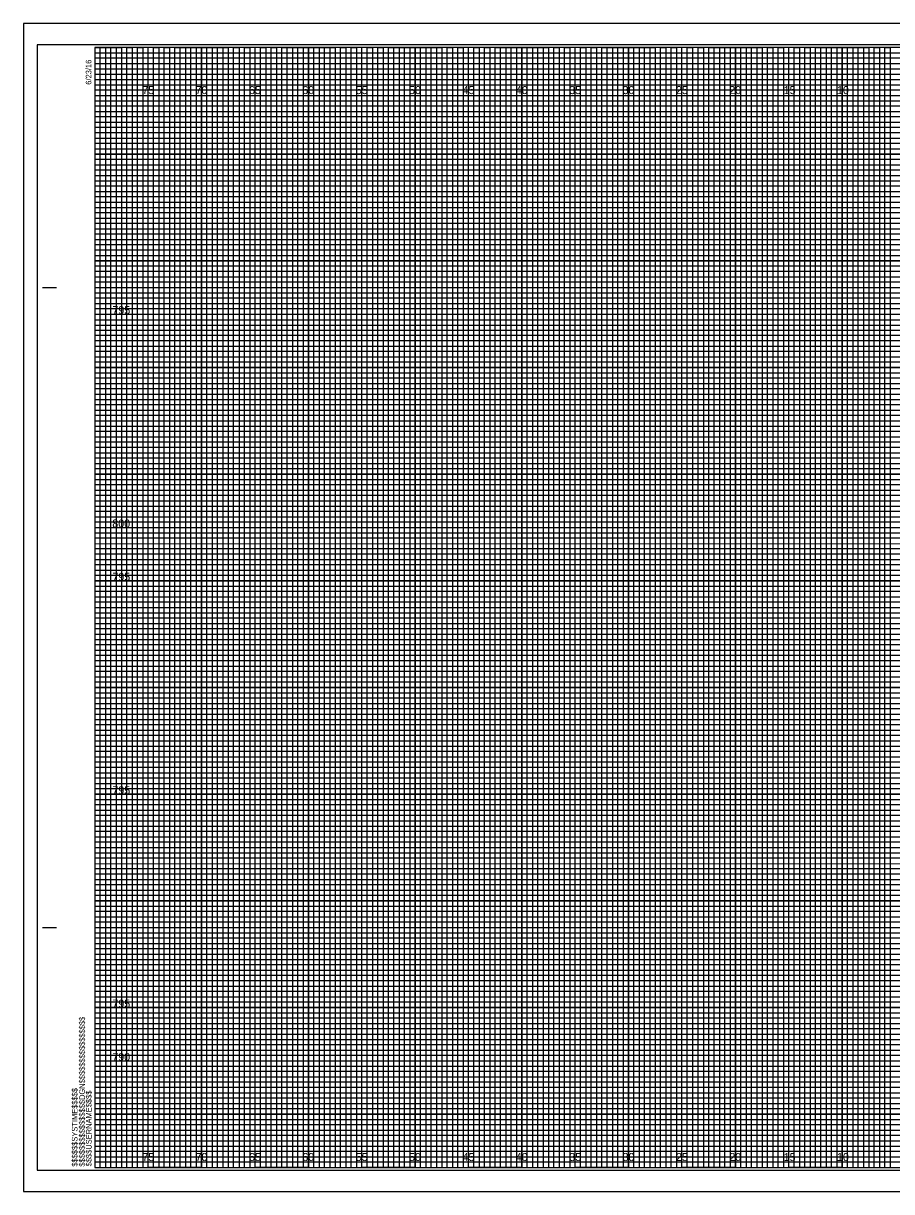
# Model space of a CAD drawing. Extents: x -7 to 162, y -2 to 107.
# Drawn here: x -6.7 to 74.6, y -2.3 to 107.3 of the extents above; entities that cross this region are included whole.
import ezdxf

# ---------------------------------------------------------------- set-up
doc = ezdxf.new("R2010")
doc.units = 0
for name, color, linetype in [('Exist Cross Section Cell', 7, 'Continuous'), ('Exist XS Center Line Elevation Label', 7, 'Continuous'), ('Prop CMT Pvmt Course 2 Wedge', 7, 'Continuous'), ('Prop CMT Pvmt Surface Shoulder', 7, 'Continuous'), ('Prop CMT Shld Paved Course 1', 7, 'Continuous'), ('Prop CMT Shld Paved Course 3', 7, 'Continuous'), ('Prop XS Hydro Elevations', 7, 'Continuous'), ('Prop XS SE Text', 7, 'Continuous'), ('Prop XS Side Slope Text', 7, 'Continuous'), ('Sheet Cutting Line CELL', 7, 'Continuous'), ('Sheet DOT Grid CELL', 7, 'Continuous')]:
    doc.layers.add(name, color=color, linetype=linetype)

msp = doc.modelspace()

# ---------------------------------------------------------------- linework, layer by layer
at = {"layer": 'Exist Cross Section Cell'}
for p, q in [((5, 105), (0, 105)), ((5, 0), (5, 105)), ((15, 105), (10, 105)), ((10, 105), (10, 0)), ((15, 0), (15, 105)), ((25, 105), (20, 105)), ((20, 105), (20, 0)), ((25, 0), (25, 105)), ((35, 105), (30, 105)), ((30, 105), (30, 0)), ((35, 0), (35, 105)), ((45, 105), (40, 105)), ((40, 105), (40, 0)), ((45, 0), (45, 105)), ((55, 105), (50, 105)), ((50, 105), (50, 0)), ((55, 0), (55, 105)), ((65, 105), (60, 105)), ((60, 105), (60, 0)), ((65, 0), (65, 105)), ((75, 105), (70, 105)), ((70, 105), (70, 0)), ((10, 0), (5, 0)), ((20, 0), (15, 0)), ((30, 0), (25, 0)), ((40, 0), (35, 0)), ((50, 0), (45, 0)), ((60, 0), (55, 0)), ((70, 0), (65, 0))]:
    msp.add_line(p, q, dxfattribs=at)
for points in [[(0, 100), (160, 100), (160, 95), (0, 95)], [(0, 90), (160, 90), (160, 85), (0, 85)], [(0, 80), (160, 80), (160, 75), (0, 75)], [(0, 70), (160, 70), (160, 65), (0, 65)], [(0, 60), (160, 60), (160, 55), (0, 55)], [(0, 50), (160, 50), (160, 45), (0, 45)], [(0, 40), (160, 40), (160, 35), (0, 35)], [(0, 30), (160, 30), (160, 25), (0, 25)], [(0, 20), (160, 20), (160, 15), (0, 15)], [(0, 10), (160, 10), (160, 5), (0, 5)]]:
    msp.add_lwpolyline(points, dxfattribs=at)
at = {"layer": 'Exist XS Center Line Elevation Label'}
for points in [[(0, 105), (2.5, 105), (2.5, 0), (7.5, 0), (7.5, 105), (12.5, 105), (12.5, 0), (17.5, 0), (17.5, 105), (22.5, 105), (22.5, 0), (27.5, 0), (27.5, 105), (32.5, 105), (32.5, 0), (37.5, 0), (37.5, 105), (42.5, 105), (42.5, 0), (47.5, 0), (47.5, 105), (52.5, 105), (52.5, 0), (57.5, 0), (57.5, 105), (62.5, 105), (62.5, 0), (67.5, 0), (67.5, 105), (72.5, 105), (72.5, 0), (77.5, 0)], [(0, 102.5), (137.5, 102.5)], [(0, 92.5), (160, 92.5), (160, 97.5), (0, 97.5)], [(0, 82.5), (160, 82.5), (160, 87.5), (0, 87.5)], [(0, 72.5), (160, 72.5), (160, 77.5), (0, 77.5)], [(0, 62.5), (160, 62.5), (160, 67.5), (0, 67.5)], [(0, 52.5), (160, 52.5), (160, 57.5), (0, 57.5)], [(0, 42.5), (160, 42.5), (160, 47.5), (0, 47.5)], [(0, 32.5), (160, 32.5), (160, 37.5), (0, 37.5)], [(0, 22.5), (160, 22.5), (160, 27.5), (0, 27.5)], [(0, 12.5), (160, 12.5), (160, 17.5), (0, 17.5)], [(0, 2.5), (160, 2.5), (160, 7.5), (0, 7.5)]]:
    msp.add_lwpolyline(points, dxfattribs=at)
at = {"layer": 'Prop CMT Pvmt Surface Shoulder'}
msp.add_lwpolyline([(-5.4, -0.25), (161.2, -0.25), (161.2, 105.25), (-5.4, 105.25)], close=True, dxfattribs=at)
at = {"layer": 'Prop CMT Shld Paved Course 1'}
for points in [[(0, 0), (0.5, 0), (0.5, 105), (1, 105), (1, 0)], [(1, 0), (1.5, 0), (1.5, 105), (2, 105), (2, 0)], [(2.5, 0), (3, 0), (3, 105), (3.5, 105), (3.5, 0)], [(3.5, 0), (4, 0), (4, 105), (4.5, 105), (4.5, 0)], [(5, 0), (5.5, 0), (5.5, 105), (6, 105), (6, 0)], [(6, 0), (6.5, 0), (6.5, 105), (7, 105), (7, 0)], [(7.5, 0), (8, 0), (8, 105), (8.5, 105), (8.5, 0)], [(8.5, 0), (9, 0), (9, 105), (9.5, 105), (9.5, 0)], [(10, 0), (10.5, 0), (10.5, 105), (11, 105), (11, 0)], [(11, 0), (11.5, 0), (11.5, 105), (12, 105), (12, 0)], [(12.5, 0), (13, 0), (13, 105), (13.5, 105), (13.5, 0)], [(13.5, 0), (14, 0), (14, 105), (14.5, 105), (14.5, 0)], [(15, 0), (15.5, 0), (15.5, 105), (16, 105), (16, 0)], [(16, 0), (16.5, 0), (16.5, 105), (17, 105), (17, 0)], [(17.5, 0), (18, 0), (18, 105), (18.5, 105), (18.5, 0)], [(18.5, 0), (19, 0), (19, 105), (19.5, 105), (19.5, 0)], [(20, 0), (20.5, 0), (20.5, 105), (21, 105), (21, 0)], [(21, 0), (21.5, 0), (21.5, 105), (22, 105), (22, 0)], [(22.5, 0), (23, 0), (23, 105), (23.5, 105), (23.5, 0)], [(23.5, 0), (24, 0), (24, 105), (24.5, 105), (24.5, 0)], [(25, 0), (25.5, 0), (25.5, 105), (26, 105), (26, 0)], [(26, 0), (26.5, 0), (26.5, 105), (27, 105), (27, 0)], [(27.5, 0), (28, 0), (28, 105), (28.5, 105), (28.5, 0)], [(28.5, 0), (29, 0), (29, 105), (29.5, 105), (29.5, 0)], [(30, 0), (30.5, 0), (30.5, 105), (31, 105), (31, 0)], [(31, 0), (31.5, 0), (31.5, 105), (32, 105), (32, 0)], [(32.5, 0), (33, 0), (33, 105), (33.5, 105), (33.5, 0)], [(33.5, 0), (34, 0), (34, 105), (34.5, 105), (34.5, 0)], [(35, 0), (35.5, 0), (35.5, 105), (36, 105), (36, 0)], [(36, 0), (36.5, 0), (36.5, 105), (37, 105), (37, 0)], [(37.5, 0), (38, 0), (38, 105), (38.5, 105), (38.5, 0)], [(38.5, 0), (39, 0), (39, 105), (39.5, 105), (39.5, 0)], [(40, 0), (40.5, 0), (40.5, 105), (41, 105), (41, 0)], [(41, 0), (41.5, 0), (41.5, 105), (42, 105), (42, 0)], [(42.5, 0), (43, 0), (43, 105), (43.5, 105), (43.5, 0)], [(43.5, 0), (44, 0), (44, 105), (44.5, 105), (44.5, 0)], [(45, 0), (45.5, 0), (45.5, 105), (46, 105), (46, 0)], [(46, 0), (46.5, 0), (46.5, 105), (47, 105), (47, 0)], [(47.5, 0), (48, 0), (48, 105), (48.5, 105), (48.5, 0)], [(48.5, 0), (49, 0), (49, 105), (49.5, 105), (49.5, 0)], [(50, 0), (50.5, 0), (50.5, 105), (51, 105), (51, 0)], [(51, 0), (51.5, 0), (51.5, 105), (52, 105), (52, 0)], [(52.5, 0), (53, 0), (53, 105), (53.5, 105), (53.5, 0)], [(53.5, 0), (54, 0), (54, 105), (54.5, 105), (54.5, 0)], [(55, 0), (55.5, 0), (55.5, 105), (56, 105), (56, 0)], [(56, 0), (56.5, 0), (56.5, 105), (57, 105), (57, 0)], [(57.5, 0), (58, 0), (58, 105), (58.5, 105), (58.5, 0)], [(58.5, 0), (59, 0), (59, 105), (59.5, 105), (59.5, 0)], [(60, 0), (60.5, 0), (60.5, 105), (61, 105), (61, 0)], [(61, 0), (61.5, 0), (61.5, 105), (62, 105), (62, 0)], [(62.5, 0), (63, 0), (63, 105), (63.5, 105), (63.5, 0)], [(63.5, 0), (64, 0), (64, 105), (64.5, 105), (64.5, 0)], [(65, 0), (65.5, 0), (65.5, 105), (66, 105), (66, 0)], [(66, 0), (66.5, 0), (66.5, 105), (67, 105), (67, 0)], [(67.5, 0), (68, 0), (68, 105), (68.5, 105), (68.5, 0)], [(68.5, 0), (69, 0), (69, 105), (69.5, 105), (69.5, 0)], [(70, 0), (70.5, 0), (70.5, 105), (71, 105), (71, 0)], [(71, 0), (71.5, 0), (71.5, 105), (72, 105), (72, 0)], [(72.5, 0), (73, 0), (73, 105), (73.5, 105), (73.5, 0)], [(73.5, 0), (74, 0), (74, 105), (74.5, 105), (74.5, 0)]]:
    msp.add_lwpolyline(points, dxfattribs=at)
at = {"layer": 'Prop CMT Shld Paved Course 3'}
msp.add_lwpolyline([(-6.7, -2.25), (161.65, -2.25), (161.65, 107.25), (-6.7, 107.25)], close=True, dxfattribs=at)
at = {"layer": 'Prop XS Hydro Elevations'}
for p, q in [((-4.9, 82.5), (-3.65, 82.5)), ((-4.85, 82.5), (-3.6, 82.5)), ((-4.9, 22.5), (-3.65, 22.5)), ((-4.85, 22.5), (-3.6, 22.5)), ((0, 0), (0, 0)), ((0, 0), (0, 0)), ((0, 0), (0, 0)), ((0, 0), (0, 0)), ((0, 0), (0, 0)), ((0, 0), (0, 0)), ((0, 0), (0, 0))]:
    msp.add_line(p, q, dxfattribs=at)
msp.add_lwpolyline([(160, 105), (0, 105), (0, 0), (160, 0)], close=True, dxfattribs=at)
at = {"layer": 'Prop XS Side Slope Text'}
for p, q in [((0, 104.5), (130, 104.5)), ((130, 103.99), (0, 103.99)), ((0, 103.99), (0, 103.5)), ((0, 103.5), (130, 103.5)), ((130, 102.95), (0, 102.95)), ((0, 102.95), (0, 102)), ((0, 102), (160, 102))]:
    msp.add_line(p, q, dxfattribs=at)
for points in [[(0, 101.5), (135, 101.5), (160, 101.5), (160, 101), (0, 101)], [(0, 100.5), (160, 100.5), (160, 99.5), (0, 99.5)], [(0, 99), (160, 99), (160, 98.5), (0, 98.49)], [(0, 98), (160, 98), (160, 97), (0, 97)], [(0, 96.5), (160, 96.5), (160, 96), (0, 96)], [(0, 95.5), (160, 95.5), (160, 94.5), (0, 94.5)], [(0, 94), (160, 94), (160, 93.5), (0, 93.5)], [(0, 93), (160, 93), (160, 92), (0, 92)], [(0, 91.5), (160, 91.5), (160, 91), (0, 91)], [(0, 90.5), (160, 90.5), (160, 89.5), (0, 89.5)], [(0, 89), (160, 89), (160, 88.5), (0, 88.5)], [(0, 88), (160, 88), (160, 86.98), (160, 86.5), (160, 86), (0, 86)], [(0, 87), (160, 87), (160, 86.5), (0, 86.5)], [(0, 85.5), (160, 85.5), (160, 84.5), (0, 84.52)], [(0, 84.52), (160, 84.5), (160, 84), (0, 84)], [(0, 83.5), (160, 83.5), (160, 83), (0, 83)], [(0, 82), (160, 82), (160, 81.5), (0, 81.5)], [(0, 81), (160, 81), (160, 80.5), (0, 80.5)], [(-0.04, 79.45), (160, 79.45), (160, 78.94), (-0.04, 78.94)], [(0, 78.5), (160, 78.5), (160, 78), (0, 78)], [(0, 77), (160, 77), (160, 76.5), (0, 76.5)], [(0, 76), (160, 76), (160, 75.5), (0, 75.5)], [(0, 74.5), (160, 74.5), (160, 74), (0, 74)], [(0, 73.5), (160, 73.5), (160, 73), (0, 73)], [(0, 72), (160, 72), (160, 71.5), (0, 71.5)], [(0, 71), (160, 71), (160, 70.5), (0, 70.5)], [(0, 69.5), (160, 69.5), (160, 68.99), (0, 69)], [(0, 68.5), (160, 68.5), (160, 68), (0, 68)], [(0, 67), (160, 67), (160, 66.5), (0, 66.5)], [(0, 66), (160, 66), (160, 65.5), (0, 65.5)], [(0, 64.5), (160, 64.5), (160, 64), (0, 64)], [(0, 63.5), (160, 63.5), (160, 63), (0, 63)], [(0, 62), (160, 62), (160, 61.5), (0, 61.5)], [(0, 61), (160, 61), (160, 60.5), (0, 60.5)], [(0, 59.5), (160, 59.5), (160, 59), (0, 59)], [(0, 58.5), (160.03, 58.45), (160, 58), (0, 58)], [(0, 57), (160, 57), (160, 56.5), (0, 56.5)], [(0, 56), (160, 56), (160, 55.5), (0, 55.5)], [(0, 54.5), (160, 54.5), (160, 54), (0, 54)], [(0, 53.5), (160, 53.5), (160, 53), (0, 53)], [(0, 52), (160, 52), (160, 51.5), (0, 51.5)], [(0, 51), (160, 51), (160, 50.5), (0, 50.5)], [(0, 49.5), (160, 49.5), (160, 49), (0, 49)], [(0, 48.5), (160, 48.5), (160, 48), (0, 48)], [(0, 47), (160, 47), (160, 46.5), (0, 46.5)], [(0, 46), (160, 46), (160, 45.5), (0, 45.5)], [(0, 44.5), (160, 44.5), (160, 44), (0, 44)], [(0, 43.5), (160, 43.5), (160, 43), (0, 43)], [(0, 42), (160, 42), (160, 41.5), (0, 41.5)], [(0, 41), (160, 41), (160, 40.5), (0, 40.5)], [(0, 39.5), (160, 39.5), (160, 38.99), (0, 39)], [(0, 38.5), (160, 38.5), (160, 38), (0, 38)], [(0, 37), (160, 37), (160, 36.5), (0, 36.5)], [(0, 36), (160, 36), (160, 35.5), (0, 35.5)], [(0, 34.5), (160, 34.5), (160, 34), (0, 34)], [(0, 33.5), (160, 33.5), (160, 33), (0, 33)], [(0, 32), (160, 32), (160, 31.5), (0, 31.5)], [(0, 31), (160, 31), (160, 30.5), (0, 30.5)], [(0, 29.5), (160, 29.5), (160, 29), (0, 29)], [(0, 28.5), (160.03, 28.46), (160, 28), (0, 28)], [(0, 27), (160, 27), (160, 26.5), (0, 26.5)], [(0, 26), (160, 26), (160, 25.5), (0, 25.5)], [(0, 24.5), (160, 24.5), (160, 24), (0, 24)], [(0, 23.5), (160, 23.5), (160, 23), (0, 23)], [(0, 22), (160, 22), (160, 21.5), (0, 21.5)], [(0, 21), (160, 21), (160, 20.5), (0, 20.5)], [(0, 19.5), (160, 19.5), (160, 19), (0, 19)], [(0, 18.5), (160, 18.5), (160, 18), (0, 18)], [(0, 17), (160, 17), (160, 16.5), (0, 16.5)], [(0, 16), (160, 16), (160, 15.5), (0, 15.5)], [(0, 14.5), (160, 14.5), (160, 14), (0, 14)], [(0, 13.5), (160, 13.5), (160, 13), (0, 13)], [(0, 12), (160, 12), (160, 11.5), (0, 11.5)], [(0, 11), (160, 11), (160, 10.5), (0, 10.5)], [(0, 9.5), (160, 9.5), (160, 9), (0, 9)], [(0, 8.5), (160, 8.5), (160, 8), (0, 8)], [(0, 7), (160, 7), (160, 6.5), (0, 6.5)], [(0, 6), (160, 6), (160, 5.5), (0, 5.5)], [(0, 4.5), (160, 4.5), (160, 4), (0, 4)], [(0, 3.5), (160, 3.5), (160, 3), (0, 3)], [(0, 2), (160, 2), (160, 1.5), (0, 1.5)], [(0, 1), (160, 1), (160, 0.5), (0, 0.5)]]:
    msp.add_lwpolyline(points, dxfattribs=at)
at = {"layer": 'Sheet Cutting Line CELL'}
for p, q in [((161.65, 107.25), (-6.7, 107.25)), ((-6.7, 107.25), (-6.7, -2.25)), ((-6.7, -2.25), (161.65, -2.25))]:
    msp.add_line(p, q, dxfattribs=at)
at = {"layer": 'Sheet DOT Grid CELL'}
for p, q in [((5, 0), (5, 105)), ((10, 0), (10, 105)), ((15, 0), (15, 105)), ((20, 0), (20, 105)), ((25, 0), (25, 105)), ((30, 0), (30, 105)), ((35, 0), (35, 105)), ((40, 0), (40, 105)), ((45, 0), (45, 105)), ((50, 0), (50, 105)), ((55, 0), (55, 105)), ((60, 0), (60, 105)), ((65, 0), (65, 105)), ((70, 0), (70, 105)), ((0, 100), (160, 100)), ((0, 95), (160, 95)), ((0, 90), (160, 90)), ((0, 85), (160, 85)), ((0, 80), (160, 80)), ((0, 75), (160, 75)), ((0, 70), (160, 70)), ((0, 65), (160, 65)), ((0, 60), (160, 60)), ((0, 55), (160, 55)), ((0, 50), (160, 50)), ((0, 45), (160, 45)), ((0, 40), (160, 40)), ((0, 35), (160, 35)), ((0, 30), (160, 30)), ((0, 25), (160, 25)), ((0, 20), (160, 20)), ((0, 15), (160, 15)), ((0, 10), (160, 10)), ((0, 5), (160, 5))]:
    msp.add_line(p, q, dxfattribs=at)

# ---------------------------------------------------------------- texts
at = {"layer": 'Prop CMT Pvmt Course 2 Wedge'}
for s, p in [('795', (1.64, 80)), ('800', (1.63, 60)), ('795', (1.64, 55)), ('795', (1.64, 35)), ('795', (1.64, 15)), ('790', (1.63, 10))]:
    msp.add_text(s, height=0.75, dxfattribs=at).set_placement(p)
at = {"layer": 'Prop XS Hydro Elevations'}
for s, p in [('6/23/16', (-0.33, 101.5)), ('$$$$$$$$$$$$$$$$DGN$$$$$$$$$$$$$$$$', (-0.94, 0.09)), ('$$$$$$SYSTIME$$$$$', (-1.63, 0.09)), ('$$$$USERNAME$$$$', (-0.31, 0.12))]:
    msp.add_text(s, height=0.525, rotation=90, dxfattribs=at).set_placement(p)
at = {"layer": 'Prop XS SE Text'}
for s, p in [('75', (4.44, 100.62)), ('70', (9.43, 100.62)), ('65', (14.44, 100.62)), ('60', (19.43, 100.62)), ('55', (24.44, 100.62)), ('50', (29.43, 100.62)), ('45', (34.44, 100.62)), ('40', (39.43, 100.62)), ('35', (44.44, 100.62)), ('30', (49.43, 100.62)), ('25', (54.44, 100.62)), ('20', (59.43, 100.62)), ('15', (64.53, 100.62)), ('10', (69.52, 100.62)), ('75', (4.44, 0.62)), ('70', (9.43, 0.62)), ('65', (14.44, 0.62)), ('60', (19.43, 0.62)), ('55', (24.44, 0.62)), ('50', (29.43, 0.62)), ('45', (34.44, 0.62)), ('40', (39.43, 0.62)), ('35', (44.44, 0.62)), ('30', (49.43, 0.62)), ('25', (54.44, 0.62)), ('20', (59.43, 0.62)), ('15', (64.53, 0.62)), ('10', (69.52, 0.62))]:
    msp.add_text(s, height=0.75, dxfattribs=at).set_placement(p)

doc.saveas('drawing.dxf')
